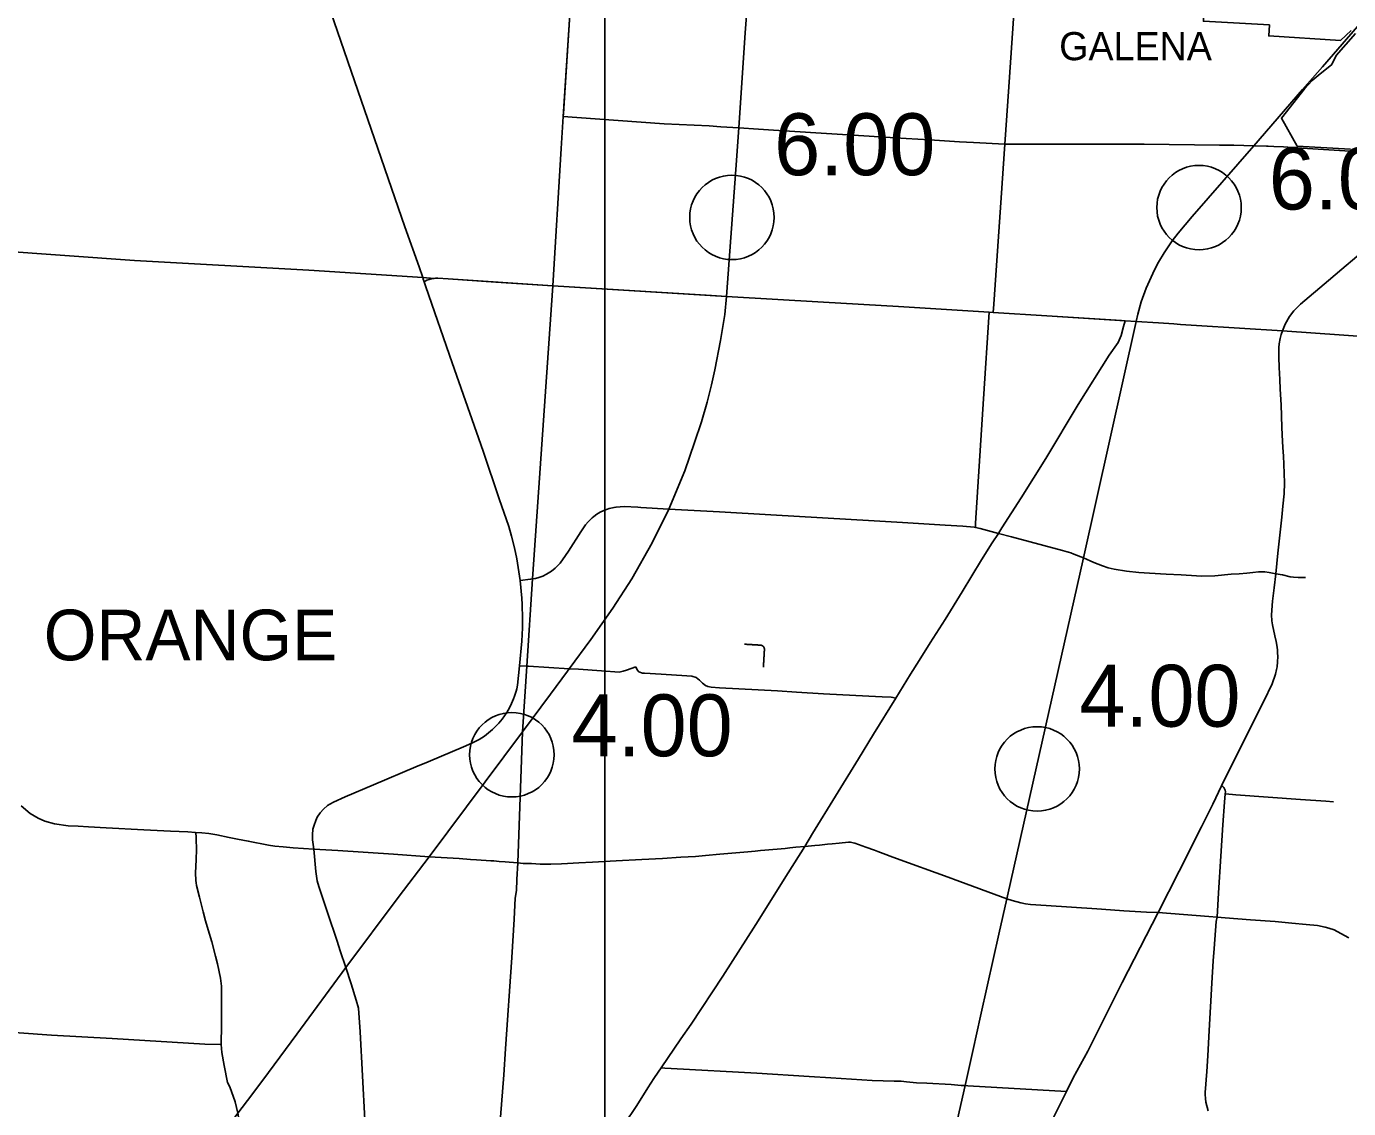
# Model space of a CAD drawing. Extents: x 1659811 to 1934326, y 644115 to 934867.
# Drawn here: x 1835797 to 1859282, y 790558 to 809790 of the extents above; entities that cross this region are included whole.
import ezdxf

# ---------------------------------------------------------------- set-up
doc = ezdxf.new("R2010")
doc.units = 0
for name, color, linetype in [('Default', 7, 'Continuous'), ('GM_X_Corporation', 7, 'Continuous'), ('GM_X_Corporation_Text', 7, 'Continuous'), ('GM_X_County_Road', 7, 'Continuous'), ('GM_X_Interstate_Route', 7, 'Continuous'), ('GM_X_State_Route', 7, 'Continuous'), ('GM_X_Township', 7, 'Continuous'), ('GM_X_Township_Road', 7, 'Continuous'), ('GM_X_Township_Text', 7, 'Continuous'), ('SH_Text', 7, 'Continuous')]:
    doc.layers.add(name, color=color, linetype=linetype)

msp = doc.modelspace()

# ---------------------------------------------------------------- linework, layer by layer
at = {"layer": 'Default'}
for centre in [(1856626, 806570), (1848329, 806396), (1844420, 796846), (1853750, 796595)]:
    msp.add_circle(centre, 750, dxfattribs=at)
at = {"layer": 'GM_X_Corporation'}
for points in [[(1859327, 809721), (1859138, 809540), (1857865, 809621), (1857876, 809816), (1856704, 809881), (1856773, 811076), (1856914, 813505), (1858114, 813436), (1858118, 813482), (1858535, 813283), (1858712, 812884), (1858845, 812940), (1858970, 812675), (1858813, 812629), (1858574, 812648), (1858471, 812534), (1858741, 812523), (1858864, 812540), (1858957, 812354), (1858043, 812416), (1857978, 811505), (1859535, 811404)], [(1859316, 807611), (1858367, 807661), (1858090, 808159), (1858507, 808685), (1858634, 808831), (1858740, 808916), (1858983, 809113), (1859065, 809276), (1859404, 809666)]]:
    msp.add_lwpolyline(points, dxfattribs=at)
at = {"layer": 'GM_X_County_Road'}
for points in [[(1852972, 804706), (1852981, 804856), (1853110, 806745), (1853175, 807697), (1853246, 808714), (1853530, 812876), (1853592, 813742), (1853681, 815234), (1853705, 815613), (1853731, 815995), (1853772, 816725), (1853832, 817646), (1853875, 818312), (1853892, 818538)], [(1842846, 805301), (1842837, 805328), (1842772, 805518), (1842519, 806229), (1841146, 810217), (1840928, 810827), (1840065, 813066), (1839518, 814468), (1839479, 814577), (1839387, 814825), (1839342, 814985), (1839324, 815084), (1839310, 815214), (1839307, 815315), (1839311, 815371), (1839312, 815408), (1839319, 815463), (1839325, 815513), (1839372, 815780)], [(1858107, 804378), (1858154, 804496), (1858234, 804633), (1858313, 804738), (1858376, 804801), (1858430, 804854), (1858924, 805276), (1859165, 805478), (1859431, 805702), (1859655, 805890), (1859866, 806052), (1859951, 806106), (1860001, 806134), (1860128, 806199), (1860275, 806259), (1860424, 806303), (1860542, 806330), (1860650, 806352), (1860797, 806382), (1860914, 806399), (1861033, 806421), (1861065, 806429)], [(1840901, 795167), (1840881, 795337), (1840878, 795422), (1840883, 795525), (1840907, 795596), (1840936, 795679), (1840963, 795735), (1841015, 795814), (1841074, 795882), (1841146, 795944), (1841188, 795971), (1841250, 796005), (1841459, 796098), (1841963, 796311), (1842716, 796630), (1842931, 796720), (1843559, 796986), (1843706, 797052), (1843837, 797118), (1843932, 797178), (1844005, 797233), (1844075, 797293), (1844123, 797340), (1844188, 797408), (1844248, 797481), (1844329, 797598), (1844353, 797638), (1844376, 797680), (1844415, 797758), (1844451, 797843), (1844467, 797886), (1844494, 797974), (1844505, 798018), (1844519, 798085), (1844557, 798429), (1844595, 798866), (1844607, 799102), (1844608, 799265), (1844601, 799518), (1844595, 799631), (1844566, 799941), (1844505, 800330), (1844464, 800522), (1844412, 800732), (1844363, 800904), (1844193, 801395), (1843910, 802243), (1843360, 803811), (1842894, 805162), (1842863, 805251), (1842846, 805301)], [(1852657, 800886), (1852657, 800961), (1852774, 802805), (1852798, 803172), (1852898, 804710), (1852972, 804706)], [(1857028, 796294), (1857277, 796797), (1857775, 797801), (1857924, 798107), (1857985, 798279), (1858004, 798364), (1858012, 798409), (1858022, 798500), (1858025, 798592), (1858022, 798657), (1858018, 798708), (1858012, 798758), (1857995, 798858), (1857972, 798957), (1857933, 799154), (1857922, 799227), (1857914, 799334), (1857933, 799575), (1857961, 799815), (1857988, 800064), (1858027, 800427), (1858061, 800749), (1858095, 801069), (1858116, 801266), (1858139, 801481), (1858144, 801679), (1858131, 802013), (1858124, 802154), (1858116, 802308), (1858103, 802533), (1858096, 802669), (1858083, 803067), (1858070, 803343), (1858061, 803513), (1858050, 803726), (1858044, 803915), (1858041, 804015), (1858044, 804087), (1858051, 804150), (1858068, 804244), (1858087, 804316), (1858107, 804378)], [(1844838, 799981), (1844901, 799998), (1844968, 800023), (1845033, 800054), (1845064, 800071), (1845094, 800091), (1845124, 800110), (1845190, 800164), (1845278, 800253), (1845373, 800385), (1845425, 800462), (1845644, 800809), (1845729, 800932), (1845773, 800986), (1845847, 801059), (1845874, 801080), (1845931, 801120), (1845991, 801156), (1846052, 801187), (1846116, 801212), (1846148, 801222), (1846234, 801241), (1846270, 801248), (1846343, 801255), (1846416, 801256), (1846655, 801244)], [(1846655, 801244), (1846713, 801241), (1847205, 801213), (1848107, 801161), (1849018, 801108), (1850858, 801002), (1851359, 800976), (1852118, 800926), (1852433, 800906), (1852629, 800889), (1852657, 800886), (1852736, 800868), (1853063, 800779), (1853297, 800719), (1854203, 800475), (1854282, 800454), (1854310, 800445)], [(1851239, 797854), (1851501, 798281), (1851653, 798524), (1851853, 798834), (1852115, 799249), (1852419, 799742), (1852763, 800311), (1852954, 800610), (1853063, 800779)], [(1854310, 800445), (1854348, 800433), (1854402, 800414), (1854573, 800349)], [(1854573, 800349), (1854755, 800266), (1854914, 800205), (1855015, 800169), (1855118, 800145), (1855340, 800109), (1855555, 800083), (1855746, 800073), (1856041, 800054), (1856308, 800043), (1856579, 800027), (1856677, 800021), (1856906, 800027), (1857196, 800056), (1857340, 800059), (1857473, 800073), (1857580, 800087), (1857682, 800095), (1857756, 800098), (1857798, 800096), (1857874, 800083), (1857988, 800064)], [(1844566, 799941), (1844753, 799964), (1844785, 799970), (1844828, 799978), (1844838, 799981)], [(1857988, 800064), (1858110, 800041), (1858246, 800011), (1858305, 800003), (1858385, 799998), (1858516, 799994)], [(1846408, 790272), (1846638, 790612), (1846837, 790928), (1846939, 791093), (1847017, 791206), (1847071, 791285), (1847419, 791795), (1847605, 792061), (1848165, 792910), (1848753, 793830), (1849328, 794748), (1849622, 795214), (1849759, 795447), (1850577, 796772), (1850846, 797211), (1851239, 797854)], [(1851209, 784694), (1851326, 784936), (1852148, 786590), (1852443, 787187), (1853141, 788601), (1853675, 789667), (1853798, 789914), (1853979, 790280), (1854272, 790859), (1854392, 791103), (1854649, 791581), (1855260, 792799), (1855898, 794041), (1856273, 794777), (1856673, 795566), (1856869, 795971), (1857028, 796294)], [(1856946, 793960), (1856946, 793960), (1856971, 794394), (1857013, 795045), (1857051, 795598), (1857080, 796004), (1857092, 796153), (1857094, 796187), (1857090, 796216), (1857080, 796243), (1857067, 796263), (1857051, 796280), (1857028, 796294)], [(1835702, 795941), (1835860, 795804), (1836005, 795717), (1836126, 795665), (1836296, 795616), (1836540, 795586), (1836718, 795575), (1836898, 795565), (1837211, 795550), (1837882, 795514), (1838358, 795490), (1838663, 795475), (1838800, 795467), (1838912, 795460), (1839037, 795444), (1839177, 795424), (1839395, 795378), (1839546, 795348), (1839738, 795311), (1840094, 795242), (1840210, 795224), (1840358, 795207), (1840537, 795193), (1840901, 795167)], [(1841806, 790360), (1841726, 791923), (1841696, 792345), (1841656, 792486), (1841567, 792777), (1841473, 793063), (1841372, 793364), (1841315, 793534), (1841145, 794040), (1840989, 794505), (1840960, 794607), (1840938, 794769), (1840901, 795167)], [(1856789, 790519), (1856749, 790673), (1856741, 790738), (1856737, 790808), (1856738, 790844), (1856763, 791215), (1856781, 791498), (1856809, 791946), (1856855, 792786), (1856879, 793181), (1856895, 793405), (1856933, 793880), (1856936, 793913), (1856946, 793960)]]:
    msp.add_lwpolyline(points, dxfattribs=at)
at = {"layer": 'GM_X_Interstate_Route'}
for points in [[(1845438, 798374), (1845825, 798892), (1846211, 799449), (1846552, 799972), (1846911, 800613), (1847205, 801213), (1847493, 801891), (1847666, 802395), (1847786, 802765), (1847888, 803110), (1847964, 803419), (1848028, 803685), (1848125, 804211), (1848200, 804670), (1848231, 804991), (1848401, 807248), (1848453, 807987), (1848565, 809674), (1848656, 810925)], [(1837487, 786429), (1837514, 786520), (1837601, 786793), (1837756, 787221), (1837932, 787687), (1838187, 788245), (1838424, 788716), (1838589, 789007), (1838800, 789367), (1839053, 789775), (1839282, 790094), (1839487, 790389), (1839554, 790475), (1839800, 790800), (1840096, 791202), (1840599, 791880), (1841473, 793063), (1842402, 794310), (1842953, 795035), (1844609, 797255), (1845106, 797922), (1845407, 798332)], [(1845407, 798332), (1845438, 798374)]]:
    msp.add_lwpolyline(points, dxfattribs=at)
at = {"layer": 'GM_X_State_Route'}
for points in [[(1853225, 794338), (1854573, 800349), (1855512, 804546), (1855541, 804679), (1855596, 804898), (1855689, 805139), (1855836, 805465), (1855908, 805599), (1856008, 805767), (1856148, 805978), (1856255, 806119), (1856504, 806413), (1857597, 807668), (1858467, 808668), (1858818, 809072), (1859440, 809788), (1860025, 810459)], [(1851027, 784561), (1851027, 784562), (1851101, 784861), (1851390, 786171), (1851399, 786214), (1851899, 788445), (1852470, 790966), (1852613, 791609), (1852746, 792202), (1852871, 792760), (1853072, 793659), (1853214, 794287), (1853225, 794338)]]:
    msp.add_lwpolyline(points, dxfattribs=at)
at = {"layer": 'GM_X_Township'}
for points in [[(1846971, 832575), (1846863, 830918), (1846854, 830870), (1846509, 825988), (1846205, 821378), (1845900, 816686), (1845813, 815443), (1845687, 813540), (1845670, 813309), (1845637, 812811), (1845452, 810003), (1845333, 808188), (1845296, 807619), (1845145, 805182), (1843287, 805303), (1843103, 805315), (1843041, 805313), (1842837, 805328), (1840812, 805456), (1837716, 805633), (1832763, 805986)], [(1843918, 786568), (1844278, 791160), (1844305, 791617), (1844418, 793241), (1844463, 793924), (1844479, 794298), (1844500, 794432), (1844507, 794629), (1844527, 794924), (1844609, 797255), (1844685, 798421), (1844785, 799970), (1845145, 805182), (1848231, 804991), (1849953, 804892), (1851286, 804810), (1852898, 804710), (1852972, 804706), (1853920, 804647), (1855314, 804559), (1855512, 804546), (1855904, 804520), (1856177, 804502), (1856300, 804491), (1856579, 804475), (1858107, 804378), (1864561, 803926)]]:
    msp.add_lwpolyline(points, dxfattribs=at)
at = {"layer": 'GM_X_Township_Road'}
for points in [[(1845336, 808240), (1845452, 810003), (1845637, 812811), (1845670, 813309), (1845687, 813540), (1845813, 815443)], [(1845145, 805182), (1845296, 807619), (1845333, 808188), (1845336, 808240)], [(1845333, 808188), (1845902, 808151), (1847128, 808058), (1847922, 808022), (1848130, 808008), (1848453, 807987), (1848798, 807964), (1849069, 807946), (1851423, 807800), (1851838, 807775), (1852372, 807742), (1852621, 807728), (1853175, 807697)], [(1853175, 807697), (1854218, 807699), (1855651, 807697), (1856991, 807682), (1857244, 807678), (1857423, 807675), (1857597, 807668)], [(1857597, 807668), (1857597, 807668), (1857824, 807663), (1857853, 807662)], [(1857853, 807662), (1857956, 807657), (1858128, 807649), (1858365, 807634), (1858840, 807601), (1860259, 807513), (1860357, 807502), (1860647, 807487), (1860662, 807487)], [(1842863, 805251), (1842909, 805278), (1842951, 805293), (1842996, 805306), (1843041, 805313), (1843065, 805314)], [(1843065, 805314), (1843103, 805315), (1843287, 805303), (1844132, 805248)], [(1844132, 805248), (1845145, 805182)], [(1845145, 805182), (1847965, 805008)], [(1847965, 805008), (1848231, 804991), (1849953, 804892), (1851286, 804810), (1852898, 804710)], [(1852972, 804706), (1853920, 804647), (1855248, 804563)], [(1853063, 800779), (1853085, 800818), (1853124, 800877), (1853467, 801413), (1853904, 802110), (1854482, 803071), (1855027, 803947), (1855187, 804174), (1855245, 804296), (1855285, 804458), (1855314, 804559)], [(1855248, 804563), (1855314, 804559), (1855512, 804546)], [(1855512, 804546), (1855904, 804520), (1856177, 804502), (1856300, 804491), (1856579, 804475), (1858107, 804378)], [(1848887, 798403), (1848888, 798408), (1848888, 798411), (1848888, 798413), (1848888, 798415), (1848888, 798418), (1848888, 798420), (1848889, 798423), (1848889, 798425), (1848889, 798427), (1848889, 798430), (1848889, 798432), (1848889, 798435), (1848889, 798437), (1848890, 798440), (1848890, 798442), (1848890, 798444), (1848890, 798447), (1848890, 798449), (1848890, 798452), (1848890, 798454), (1848891, 798457), (1848891, 798459), (1848891, 798461), (1848891, 798464), (1848891, 798466), (1848891, 798469), (1848891, 798471), (1848892, 798473), (1848892, 798476), (1848892, 798478), (1848892, 798481), (1848892, 798483), (1848892, 798486), (1848893, 798488), (1848893, 798491), (1848893, 798493), (1848893, 798496), (1848893, 798498), (1848893, 798501), (1848893, 798503), (1848894, 798506), (1848894, 798508), (1848894, 798511), (1848894, 798513), (1848894, 798516), (1848894, 798518), (1848894, 798521), (1848895, 798523), (1848895, 798526), (1848895, 798528), (1848895, 798531), (1848895, 798533), (1848895, 798535), (1848896, 798538), (1848896, 798540), (1848896, 798543), (1848896, 798545), (1848896, 798548), (1848896, 798550), (1848896, 798553), (1848897, 798555), (1848897, 798558), (1848897, 798560), (1848897, 798563), (1848897, 798565), (1848897, 798568), (1848897, 798570), (1848898, 798573), (1848898, 798575), (1848898, 798578), (1848898, 798580), (1848898, 798583), (1848898, 798585), (1848899, 798588), (1848899, 798590), (1848899, 798593), (1848899, 798595), (1848899, 798598), (1848899, 798600), (1848899, 798603), (1848900, 798605), (1848900, 798608), (1848900, 798610), (1848900, 798612), (1848900, 798615), (1848900, 798617), (1848900, 798620), (1848901, 798622), (1848901, 798625), (1848901, 798627), (1848901, 798630), (1848901, 798632), (1848901, 798635), (1848902, 798637), (1848902, 798640), (1848902, 798642), (1848902, 798645), (1848902, 798647), (1848902, 798650), (1848902, 798652), (1848903, 798655), (1848903, 798657), (1848903, 798660), (1848903, 798662), (1848903, 798665), (1848903, 798667), (1848903, 798670), (1848904, 798672), (1848904, 798675), (1848904, 798677), (1848904, 798680), (1848904, 798682), (1848904, 798685), (1848905, 798687), (1848905, 798690), (1848905, 798692), (1848905, 798694), (1848905, 798697), (1848905, 798699), (1848905, 798702), (1848906, 798704), (1848906, 798707), (1848906, 798709), (1848906, 798712), (1848906, 798714), (1848906, 798715), (1848906, 798716), (1848906, 798718), (1848906, 798719), (1848906, 798720), (1848906, 798722), (1848906, 798723), (1848906, 798724), (1848906, 798725), (1848906, 798727), (1848906, 798728), (1848906, 798729), (1848905, 798731), (1848905, 798732), (1848905, 798733), (1848905, 798734), (1848904, 798736), (1848904, 798737), (1848904, 798738), (1848903, 798740), (1848903, 798741), (1848903, 798742), (1848902, 798743), (1848902, 798745), (1848901, 798746), (1848901, 798747), (1848900, 798748), (1848900, 798749), (1848899, 798751), (1848899, 798752), (1848898, 798753), (1848898, 798754), (1848897, 798755), (1848896, 798756), (1848896, 798758), (1848895, 798759), (1848894, 798760), (1848893, 798761), (1848893, 798762), (1848892, 798763), (1848891, 798764), (1848890, 798765), (1848890, 798766), (1848889, 798767), (1848888, 798768), (1848887, 798769), (1848886, 798770), (1848885, 798771), (1848884, 798772), (1848883, 798773), (1848882, 798774), (1848881, 798775), (1848881, 798775), (1848880, 798776), (1848879, 798777), (1848877, 798778), (1848876, 798779), (1848875, 798780), (1848874, 798780), (1848873, 798781), (1848872, 798782), (1848871, 798782), (1848870, 798783), (1848869, 798784), (1848868, 798784), (1848867, 798785), (1848865, 798786), (1848864, 798786), (1848863, 798787), (1848862, 798787), (1848861, 798788), (1848859, 798788), (1848858, 798789), (1848857, 798789), (1848856, 798790), (1848854, 798790), (1848853, 798791), (1848852, 798791), (1848851, 798791), (1848849, 798792), (1848848, 798792), (1848847, 798792), (1848846, 798792), (1848844, 798793), (1848843, 798793), (1848842, 798793), (1848840, 798793), (1848839, 798793), (1848838, 798794), (1848837, 798794), (1848836, 798794), (1848833, 798794), (1848831, 798794), (1848828, 798794), (1848826, 798794), (1848823, 798794), (1848821, 798795), (1848818, 798795), (1848816, 798795), (1848813, 798795), (1848811, 798795), (1848808, 798795), (1848806, 798796), (1848803, 798796), (1848801, 798796), (1848798, 798796), (1848796, 798796), (1848793, 798796), (1848791, 798796), (1848788, 798797), (1848786, 798797), (1848783, 798797), (1848781, 798797), (1848778, 798797), (1848776, 798797), (1848773, 798797), (1848771, 798798), (1848768, 798798), (1848766, 798798), (1848763, 798798), (1848761, 798798), (1848758, 798798), (1848756, 798799), (1848753, 798799), (1848751, 798799), (1848748, 798799), (1848746, 798799), (1848744, 798799), (1848741, 798799), (1848739, 798800), (1848736, 798800), (1848734, 798800), (1848731, 798800), (1848729, 798800), (1848726, 798800), (1848724, 798801), (1848721, 798801), (1848719, 798801), (1848716, 798801), (1848714, 798801), (1848711, 798801), (1848709, 798801), (1848706, 798802), (1848704, 798802), (1848701, 798802), (1848699, 798802), (1848696, 798802), (1848694, 798802), (1848691, 798802), (1848689, 798803), (1848686, 798803), (1848684, 798803), (1848681, 798803), (1848679, 798803), (1848676, 798803), (1848674, 798804), (1848671, 798804), (1848669, 798804), (1848666, 798804), (1848664, 798804), (1848661, 798804), (1848659, 798804), (1848656, 798805), (1848654, 798805), (1848651, 798805), (1848649, 798805), (1848646, 798805), (1848644, 798805), (1848641, 798805), (1848639, 798806), (1848636, 798806), (1848634, 798806), (1848631, 798806), (1848629, 798806), (1848626, 798806), (1848624, 798807), (1848621, 798807), (1848619, 798807), (1848616, 798807), (1848614, 798807), (1848611, 798807), (1848609, 798807), (1848606, 798808), (1848604, 798808), (1848601, 798808), (1848599, 798808), (1848596, 798808), (1848594, 798808), (1848591, 798808), (1848589, 798809), (1848586, 798809), (1848584, 798809), (1848581, 798809), (1848579, 798809), (1848576, 798809), (1848574, 798810), (1848571, 798810), (1848569, 798810), (1848566, 798810), (1848564, 798810), (1848561, 798810), (1848559, 798810), (1848556, 798811), (1848551, 798811)], [(1844557, 798429), (1844685, 798421), (1844713, 798419)], [(1844713, 798419), (1845438, 798374), (1845605, 798366), (1846010, 798339), (1846326, 798317), (1846396, 798331), (1846458, 798351), (1846539, 798381), (1846621, 798407)], [(1846621, 798407), (1846648, 798353), (1846677, 798319), (1846739, 798297), (1846774, 798295)], [(1846774, 798295), (1847073, 798278), (1847525, 798251), (1847618, 798241), (1847692, 798217), (1847750, 798174), (1847804, 798120), (1847860, 798079), (1847901, 798061), (1847957, 798048), (1848107, 798036), (1849140, 797980), (1849475, 797956), (1849957, 797930), (1850759, 797887), (1851000, 797878), (1851156, 797870), (1851190, 797866), (1851239, 797854)], [(1857092, 796153), (1857218, 796138), (1857278, 796132), (1858429, 796050), (1858876, 796019), (1859017, 796010)], [(1839023, 793732), (1839022, 793733), (1838980, 793892), (1838938, 794052), (1838872, 794314), (1838831, 794473), (1838829, 794481), (1838820, 794525), (1838813, 794568), (1838807, 794613), (1838802, 794749), (1838809, 794981), (1838817, 795171), (1838814, 795349), (1838809, 795404), (1838800, 795467)], [(1849356, 795191), (1849466, 795202), (1849622, 795214), (1849804, 795234), (1849882, 795241), (1850029, 795258), (1850109, 795264), (1850232, 795277), (1850401, 795291), (1850433, 795290), (1850480, 795282), (1850513, 795274), (1850642, 795228), (1850705, 795204), (1850860, 795148), (1850918, 795128), (1851016, 795091), (1851187, 795029), (1852238, 794646), (1852263, 794637)], [(1840901, 795167), (1841330, 795144), (1842317, 795078)], [(1842317, 795078), (1842953, 795035), (1843483, 795000), (1843682, 794987), (1843794, 794978), (1844046, 794963), (1844099, 794959)], [(1844518, 794925), (1844527, 794924), (1844623, 794916), (1844766, 794911), (1844921, 794904), (1844972, 794902), (1845039, 794901), (1845111, 794902), (1845300, 794907), (1845407, 794912), (1845608, 794925), (1845850, 794939), (1846270, 794960), (1846729, 794982), (1847097, 795005), (1847420, 795024), (1847682, 795038), (1847858, 795053), (1848116, 795077), (1848609, 795123), (1848741, 795134), (1848838, 795144), (1848913, 795150), (1849273, 795182), (1849356, 795191)], [(1844099, 794959), (1844196, 794951), (1844299, 794944), (1844518, 794925)], [(1852263, 794637), (1853214, 794287)], [(1853214, 794287), (1853305, 794256), (1853460, 794213), (1853545, 794199), (1853631, 794186), (1853911, 794167)], [(1853911, 794167), (1854809, 794108), (1855052, 794090), (1855289, 794075), (1855696, 794051), (1855898, 794041), (1856800, 793974), (1856946, 793960)], [(1856946, 793960), (1857092, 793949), (1857542, 793914), (1857978, 793881), (1858274, 793854), (1858527, 793830), (1858733, 793811), (1858865, 793782), (1858933, 793763), (1859024, 793732), (1859146, 793672), (1859290, 793592)], [(1839261, 792049), (1839264, 792370), (1839264, 792732), (1839243, 792874), (1839189, 793128), (1839156, 793264), (1839087, 793520), (1839023, 793732)], [(1830989, 792193), (1830989, 792193), (1831659, 792153), (1833599, 792034), (1835168, 791938), (1836243, 791862), (1837317, 791801), (1838966, 791703), (1839258, 791696)], [(1839258, 791696), (1839261, 792049)], [(1839580, 790316), (1839554, 790475), (1839505, 790679), (1839409, 790947), (1839371, 791021), (1839307, 791326), (1839267, 791553), (1839258, 791696)], [(1847071, 791285), (1847137, 791277), (1847250, 791272), (1848774, 791185), (1849701, 791130), (1850088, 791107), (1850817, 791057), (1851208, 791046), (1851334, 791044), (1851380, 791042), (1851428, 791036), (1851605, 791018), (1851790, 791011), (1852221, 790984), (1852401, 790971), (1852418, 790969)], [(1852418, 790969), (1852428, 790967), (1852470, 790966), (1852519, 790965), (1854272, 790859)]]:
    msp.add_lwpolyline(points, dxfattribs=at)
at = {"layer": 'SH_Text'}
msp.add_lwpolyline([(1741462, 842026), (1846073, 842026), (1846073, 754070), (1741462, 754070)], close=True, dxfattribs=at)

# ---------------------------------------------------------------- texts
at = {"layer": 'Default'}
for s, p in [('6.00', (1849079, 807146)), ('6.00', (1857866, 806537)), ('4.00', (1854500, 797345)), ('4.00', (1845480, 796819))]:
    msp.add_text(s, height=1100, dxfattribs=at).set_placement(p)
at = {"layer": 'GM_X_Corporation_Text'}
msp.add_text('GALENA', height=500, rotation=0, dxfattribs=at).set_placement((1854142, 809190))
at = {"layer": 'GM_X_Township_Text'}
msp.add_text('ORANGE', height=900, rotation=0, dxfattribs=at).set_placement((1836104, 798525))

doc.saveas('drawing.dxf')
